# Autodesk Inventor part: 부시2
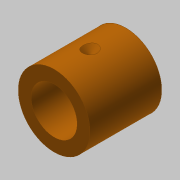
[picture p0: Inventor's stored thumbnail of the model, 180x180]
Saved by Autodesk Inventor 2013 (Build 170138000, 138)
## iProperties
Created: 2020-03
Part Number: 부시2
Material: 스테인리스강
Document SubType Name: Modeling
Designer: mduedu
Density: 1 g/cm^3
Author: mduedu
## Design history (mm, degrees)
sketch "스케치2"
  geometry: C1 r 7 at (0, 0); C2 r 4.5 at (0, 0); 1 further point
  constraints: 2 centre point, 2 coincident
  dimensions: "d15" = 14 diameter of C1; "d16" = 9 diameter of C2
extrude "돌출1" new body sketch "스케치2" distance "d17" = 14; taper "d18" = 0 deg
sketch "스케치3"
  geometry: L1 (0, -7)-(-14, -7) reference; L2 (-14, -7)-(-14, -4.5) reference; L3 (-14, -4.5)-(0, -4.5) reference; L4 (0, -4.5)-(0, -7) reference; L5 (-14, 7)-(0, 7) reference; L6 (0, 7)-(0, 4.5) reference; L7 (0, 4.5)-(-14, 4.5) reference; L8 (-14, 4.5)-(-14, 7) reference; L9 (-7, 7)-(-7, 5.5); L10 (-7, 5.5)-(-5.5, 7); L11 (-5.5, 7)-(-7, 7); 1 further point
  constraints: 6 end point, 1 collinear, 1 midpoint, 1 parallel, 1 point on line
  dimensions: "d19" = 3 diameter of L10.end L9; "d21" = 7 distance between parallel lines of L6 L9; "d22" = 45 deg angle of L10 L9
revolve "회전2" sketch "스케치3" stored, may be unused: angle "d23" = 90 deg
node "작업점1"
node "솔리드2"
node "절단 모서리 투영1"
